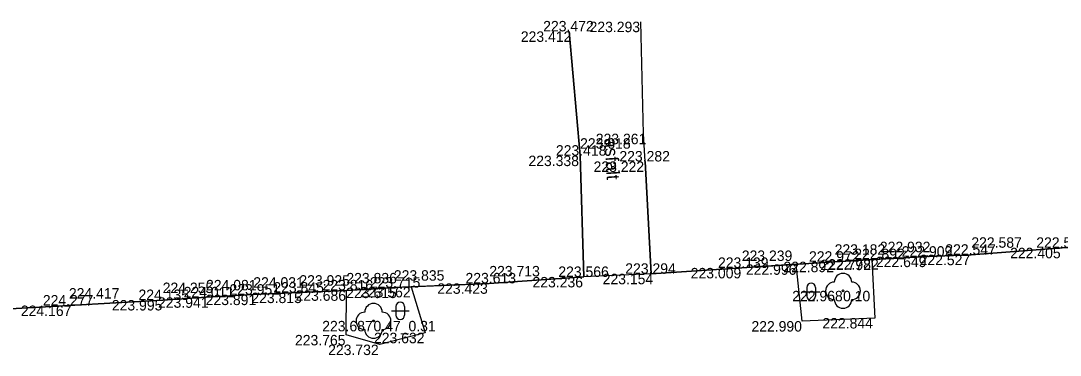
# Model space of a CAD drawing. Extents: x -599516 to -599132, y -1163668 to -1163119.
# Drawn here: x -599340.22 to -599310.39, y -1163432.23 to -1163422.63 of the extents above; entities that cross this region are included whole.
import ezdxf

# ---------------------------------------------------------------- set-up
doc = ezdxf.new("R2010")
doc.units = 0
for name, color, linetype in [('Bod-oznac1', 7, 'Continuous'), ('Bod-oznac2', 7, 'Continuous'), ('Bod-oznac3', 7, 'Continuous'), ('Bod-vyska1', 7, 'Continuous'), ('Bod-vyska2', 7, 'Continuous'), ('Bod-vyska3', 7, 'Continuous'), ('Z_cela-hrobu-dolni-linie', 7, 'Continuous'), ('Z_cela-hrobu-horni-linie', 7, 'Continuous'), ('Z_chodnik', 7, 'Continuous'), ('Z_komunikace', 7, 'Continuous'), ('Z_kultury-znacky', 7, 'Continuous'), ('Z_nove-stromy-prumer-kmene', 7, 'Continuous'), ('Z_obvod-kmene-spodek-ve-vysce1_2m', 7, 'Continuous'), ('Z_popis-budov-povrchu', 7, 'Continuous'), ('Z_stromy-kere', 7, 'Continuous'), ('Z_stromy-nove-vysazene', 7, 'Continuous')]:
    doc.layers.add(name, color=color, linetype=linetype)

msp = doc.modelspace()

# ---------------------------------------------------------------- linework, layer by layer
at = {"layer": 'Bod-oznac1'}
for p, q in [((-599322.43, -1163422.658), (-599322.43, -1163422.658)), ((-599324.484, -1163422.936), (-599324.484, -1163422.936)), ((-599322.356, -1163425.873), (-599322.356, -1163425.873)), ((-599324.172, -1163426.502), (-599324.172, -1163426.502)), ((-599322.303, -1163426.669), (-599322.303, -1163426.669)), ((-599316.867, -1163429.546), (-599316.867, -1163429.546)), ((-599315.803, -1163429.487), (-599315.803, -1163429.487)), ((-599315.569, -1163429.473), (-599315.569, -1163429.473)), ((-599314.213, -1163429.401), (-599314.213, -1163429.401)), ((-599312.945, -1163429.345), (-599312.945, -1163429.345)), ((-599322.135, -1163429.892), (-599322.135, -1163429.892)), ((-599319.532, -1163429.724), (-599319.532, -1163429.724)), ((-599317.967, -1163429.621), (-599317.967, -1163429.621)), ((-599326.777, -1163430.167), (-599326.777, -1163430.167)), ((-599324.068, -1163429.983), (-599324.068, -1163429.983)), ((-599333.55, -1163430.491), (-599333.55, -1163430.491)), ((-599332.228, -1163430.433), (-599332.228, -1163430.433)), ((-599330.879, -1163430.368), (-599330.879, -1163430.368)), ((-599329.516, -1163430.29), (-599329.516, -1163430.29)), ((-599329.015, -1163430.27), (-599329.015, -1163430.27)), ((-599316.626, -1163430.382), (-599316.626, -1163430.382)), ((-599338.841, -1163430.804), (-599338.841, -1163430.804)), ((-599336.15, -1163430.645), (-599336.15, -1163430.645)), ((-599334.906, -1163430.568), (-599334.906, -1163430.568)), ((-599330.1, -1163431.244), (-599330.1, -1163431.244)), ((-599317.798, -1163431.251), (-599317.798, -1163431.251)), ((-599315.715, -1163431.162), (-599315.715, -1163431.162)), ((-599330.882, -1163431.647), (-599330.882, -1163431.647)), ((-599328.617, -1163431.585), (-599328.617, -1163431.585)), ((-599329.919, -1163431.925), (-599329.919, -1163431.925))]:
    msp.add_line(p, q, dxfattribs=at)
at = {"layer": 'Bod-oznac2'}
for p, q in [((-599324.484, -1163422.936), (-599324.484, -1163422.936)), ((-599324.172, -1163426.502), (-599324.172, -1163426.502)), ((-599322.303, -1163426.669), (-599322.303, -1163426.669)), ((-599316.867, -1163429.546), (-599316.867, -1163429.546)), ((-599315.569, -1163429.473), (-599315.569, -1163429.473)), ((-599314.213, -1163429.401), (-599314.213, -1163429.401)), ((-599312.945, -1163429.345), (-599312.945, -1163429.345)), ((-599322.135, -1163429.892), (-599322.135, -1163429.892)), ((-599319.532, -1163429.724), (-599319.532, -1163429.724)), ((-599326.777, -1163430.167), (-599326.777, -1163430.167)), ((-599324.068, -1163429.983), (-599324.068, -1163429.983)), ((-599333.55, -1163430.491), (-599333.55, -1163430.491)), ((-599332.228, -1163430.433), (-599332.228, -1163430.433)), ((-599330.879, -1163430.368), (-599330.879, -1163430.368)), ((-599329.516, -1163430.29), (-599329.516, -1163430.29)), ((-599338.841, -1163430.804), (-599338.841, -1163430.804)), ((-599336.15, -1163430.645), (-599336.15, -1163430.645)), ((-599334.906, -1163430.568), (-599334.906, -1163430.568))]:
    msp.add_line(p, q, dxfattribs=at)
at = {"layer": 'Bod-oznac3'}
for p, q in [((-599324.172, -1163426.502), (-599324.172, -1163426.502)), ((-599316.867, -1163429.546), (-599316.867, -1163429.546)), ((-599315.569, -1163429.473), (-599315.569, -1163429.473)), ((-599312.945, -1163429.345), (-599312.945, -1163429.345)), ((-599319.532, -1163429.724), (-599319.532, -1163429.724)), ((-599326.777, -1163430.167), (-599326.777, -1163430.167)), ((-599333.55, -1163430.491), (-599333.55, -1163430.491)), ((-599332.228, -1163430.433), (-599332.228, -1163430.433)), ((-599330.879, -1163430.368), (-599330.879, -1163430.368)), ((-599329.516, -1163430.29), (-599329.516, -1163430.29)), ((-599338.841, -1163430.804), (-599338.841, -1163430.804)), ((-599336.15, -1163430.645), (-599336.15, -1163430.645)), ((-599334.906, -1163430.568), (-599334.906, -1163430.568))]:
    msp.add_line(p, q, dxfattribs=at)
at = {"layer": 'Z_cela-hrobu-dolni-linie'}
for points in [[(-599315.803, -1163429.487), (-599316.867, -1163429.546), (-599319.532, -1163429.724)], [(-599329.015, -1163430.27), (-599329.516, -1163430.29), (-599330.879, -1163430.368)]]:
    msp.add_lwpolyline(points, dxfattribs=at)
at = {"layer": 'Z_cela-hrobu-horni-linie'}
for points in [[(-599341.541, -1163430.958), (-599338.841, -1163430.804), (-599338.841, -1163430.804), (-599336.15, -1163430.645), (-599336.15, -1163430.645), (-599334.906, -1163430.568), (-599334.906, -1163430.568), (-599333.55, -1163430.491), (-599333.55, -1163430.491), (-599332.228, -1163430.433), (-599332.228, -1163430.433), (-599330.879, -1163430.368), (-599330.879, -1163430.368), (-599329.516, -1163430.29), (-599329.516, -1163430.29), (-599326.777, -1163430.167), (-599326.777, -1163430.167), (-599324.068, -1163429.983), (-599324.172, -1163426.502), (-599324.172, -1163426.502), (-599324.484, -1163422.936)], [(-599314.213, -1163429.401), (-599312.945, -1163429.345), (-599312.945, -1163429.345), (-599310.34, -1163429.147), (-599310.34, -1163429.147), (-599309.035, -1163429.074), (-599309.035, -1163429.074), (-599307.673, -1163429.034), (-599307.673, -1163429.034), (-599306.304, -1163428.934), (-599306.304, -1163428.934), (-599304.932, -1163428.858), (-599304.932, -1163428.858), (-599303.612, -1163428.781), (-599302.162, -1163428.721), (-599302.426, -1163425.479)], [(-599322.303, -1163426.669), (-599322.135, -1163429.892), (-599319.532, -1163429.724), (-599319.532, -1163429.724), (-599316.867, -1163429.546), (-599316.867, -1163429.546), (-599315.569, -1163429.473), (-599315.569, -1163429.473), (-599314.213, -1163429.401)]]:
    msp.add_lwpolyline(points, dxfattribs=at)
at = {"layer": 'Z_chodnik'}
for points in [[(-599322.135, -1163429.892), (-599322.303, -1163426.669), (-599322.356, -1163425.873), (-599322.43, -1163422.658)], [(-599324.484, -1163422.936), (-599324.172, -1163426.502), (-599324.068, -1163429.983)]]:
    msp.add_lwpolyline(points, dxfattribs=at)
at = {"layer": 'Z_komunikace'}
for points in [[(-599298.279, -1163430.316), (-599298.489, -1163428.571), (-599300.82, -1163428.686), (-599302.162, -1163428.721), (-599303.612, -1163428.781), (-599304.413, -1163428.831), (-599304.389, -1163430.505), (-599306.498, -1163430.78), (-599306.885, -1163430.504), (-599307.673, -1163429.034), (-599309.035, -1163429.074), (-599310.34, -1163429.147), (-599312.945, -1163429.345), (-599314.213, -1163429.401), (-599315.569, -1163429.473), (-599315.803, -1163429.487), (-599315.715, -1163431.162), (-599317.798, -1163431.251), (-599317.967, -1163429.621), (-599319.532, -1163429.724), (-599322.135, -1163429.892), (-599324.068, -1163429.983)], [(-599324.068, -1163429.983), (-599326.777, -1163430.167), (-599329.015, -1163430.27), (-599328.617, -1163431.585), (-599329.919, -1163431.925), (-599330.882, -1163431.647), (-599330.879, -1163430.368), (-599332.228, -1163430.433), (-599333.55, -1163430.491), (-599334.906, -1163430.568), (-599336.15, -1163430.645), (-599338.841, -1163430.804), (-599341.541, -1163430.958)]]:
    msp.add_lwpolyline(points, dxfattribs=at)
at = {"layer": 'Z_kultury-znacky'}
for p, q in [((-599317.788, -1163430.407), (-599317.288, -1163430.407)), ((-599317.663, -1163430.282), (-599317.663, -1163430.532)), ((-599317.413, -1163430.282), (-599317.413, -1163430.532)), ((-599329.581, -1163430.957), (-599329.081, -1163430.957)), ((-599329.456, -1163430.832), (-599329.456, -1163431.082)), ((-599329.206, -1163430.832), (-599329.206, -1163431.082))]:
    msp.add_line(p, q, dxfattribs=at)
for centre, start, end in [((-599317.539, -1163430.282), 0, 180), ((-599329.332, -1163430.832), 0, 180), ((-599317.539, -1163430.532), 180, 0), ((-599329.332, -1163431.082), 180, 0)]:
    msp.add_arc(centre, 0.125, start, end, dxfattribs=at)
at = {"layer": 'Z_stromy-kere'}
msp.add_circle((-599330.1, -1163431.244), 0.025, dxfattribs=at)
for centre, start, end in [((-599330.1, -1163430.994), 0, 180), ((-599330.35, -1163431.244), 90, 270), ((-599329.85, -1163431.244), 270, 90), ((-599330.1, -1163431.494), 180, 0)]:
    msp.add_arc(centre, 0.25, start, end, dxfattribs=at)
at = {"layer": 'Z_stromy-nove-vysazene'}
msp.add_circle((-599316.626, -1163430.382), 0.025, dxfattribs=at)
for centre, start, end in [((-599316.626, -1163430.132), 0, 180), ((-599316.876, -1163430.382), 90, 270), ((-599316.376, -1163430.382), 270, 90), ((-599316.626, -1163430.632), 180, 0)]:
    msp.add_arc(centre, 0.25, start, end, dxfattribs=at)

# ---------------------------------------------------------------- texts
at = {"layer": 'Bod-vyska1'}
for s, p in [('223.293', (-599323.9, -1163422.958)), ('223.412', (-599325.873, -1163423.236)), ('223.261', (-599323.722, -1163426.173)), ('223.338', (-599325.654, -1163426.802)), ('223.222', (-599323.785, -1163426.969)), ('222.405', (-599311.831, -1163429.447)), ('222.996', (-599319.414, -1163429.921)), ('222.892', (-599318.337, -1163429.846)), ('222.792', (-599317.275, -1163429.787)), ('222.782', (-599317.052, -1163429.773)), ('222.649', (-599315.683, -1163429.701)), ('222.527', (-599314.428, -1163429.645)), ('223.154', (-599323.524, -1163430.192)), ('223.009', (-599320.998, -1163430.024)), ('223.423', (-599328.27, -1163430.467)), ('223.236', (-599325.538, -1163430.283)), ('223.891', (-599334.916, -1163430.791)), ('223.815', (-599333.606, -1163430.733)), ('223.686', (-599332.338, -1163430.668)), ('223.615', (-599330.882, -1163430.59)), ('223.562', (-599330.485, -1163430.57)), ('222.968', (-599318.085, -1163430.682)), ('224.167', (-599340.22, -1163431.104)), ('223.995', (-599337.609, -1163430.945)), ('223.941', (-599336.284, -1163430.868)), ('223.687', (-599331.572, -1163431.544)), ('222.990', (-599319.255, -1163431.551)), ('222.844', (-599317.219, -1163431.462)), ('223.765', (-599332.354, -1163431.947)), ('223.632', (-599330.087, -1163431.885)), ('223.732', (-599331.402, -1163432.225))]:
    msp.add_text(s, height=0.3, dxfattribs=at).set_placement(p)
at = {"layer": 'Bod-vyska2'}
for s, p in [('223.472', (-599325.231, -1163422.936)), ('223.418', (-599324.866, -1163426.502)), ('223.282', (-599323.044, -1163426.669)), ('222.525', (-599311.081, -1163429.147)), ('222.972', (-599317.603, -1163429.546)), ('222.892', (-599316.304, -1163429.473)), ('222.909', (-599314.941, -1163429.401)), ('222.547', (-599313.692, -1163429.345)), ('223.294', (-599322.876, -1163429.892)), ('223.139', (-599320.215, -1163429.724)), ('223.613', (-599327.46, -1163430.167)), ('223.566', (-599324.797, -1163429.983)), ('223.951', (-599334.233, -1163430.491)), ('223.845', (-599332.974, -1163430.433)), ('223.816', (-599331.562, -1163430.368)), ('223.715', (-599330.206, -1163430.29)), ('224.277', (-599339.589, -1163430.804)), ('224.135', (-599336.844, -1163430.645)), ('224.011', (-599335.548, -1163430.568))]:
    msp.add_text(s, height=0.3, dxfattribs=at).set_placement(p)
at = {"layer": 'Bod-vyska3'}
for s, p in [('223.618', (-599324.172, -1163426.302)), ('222.932', (-599315.569, -1163429.273)), ('222.587', (-599312.945, -1163429.145)), ('223.239', (-599319.532, -1163429.524)), ('223.182', (-599316.867, -1163429.346)), ('223.836', (-599330.879, -1163430.168)), ('223.835', (-599329.516, -1163430.09)), ('223.713', (-599326.777, -1163429.967)), ('224.255', (-599336.15, -1163430.445)), ('224.081', (-599334.906, -1163430.368)), ('224.031', (-599333.55, -1163430.291)), ('223.925', (-599332.228, -1163430.233)), ('224.417', (-599338.841, -1163430.604))]:
    msp.add_text(s, height=0.3, dxfattribs=at).set_placement(p)
at = {"layer": 'Z_nove-stromy-prumer-kmene'}
msp.add_text('0.10', height=0.3, dxfattribs=at).set_placement((-599316.626, -1163430.682))
at = {"layer": 'Z_obvod-kmene-spodek-ve-vysce1_2m'}
msp.add_text('0.47_0.31', height=0.3, dxfattribs=at).set_placement((-599330.1, -1163431.544))
at = {"layer": 'Z_popis-budov-povrchu'}
msp.add_text('asfalt', height=0.375, rotation=273.4503, dxfattribs=at).set_placement((-599323.477, -1163426.008))

doc.saveas('drawing.dxf')
